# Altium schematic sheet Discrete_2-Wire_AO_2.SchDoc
size 431 x 279 mm; Date: Not shown in title block; ApprovedBy: Not shown in title block; CheckedBy: Not shown in title block; Author: Not shown in title block; CompanyName: Not shown in title block; Engineer: Not shown in title block; Organization: Not shown in title block; Address1: Not shown in title block; Address2: Not shown in title block; Address3: Not shown in title block; Address4: Not shown in title block; DocumentNumber: 1; Revision: Use project parameter SCH_Rev; SheetNumber: 1; SheetTotal: 1; PageSetup: Record=PageOptions|CenterHorizontal=True|CenterVertical=True|PrintScale=1.00|XCorrection=1.00|YCorrection=1.00|PrintKind=0|BorderSize=5000000|LeftOffset=0|BottomOffset=0|Orientation=2|PaperLength=1000|PaperWidth=1000|Scale=100|PaperSource=15|PrintQuality=600|MediaType=1|DitherType=10|PaperKind=Letter|PrintScaleMode=1
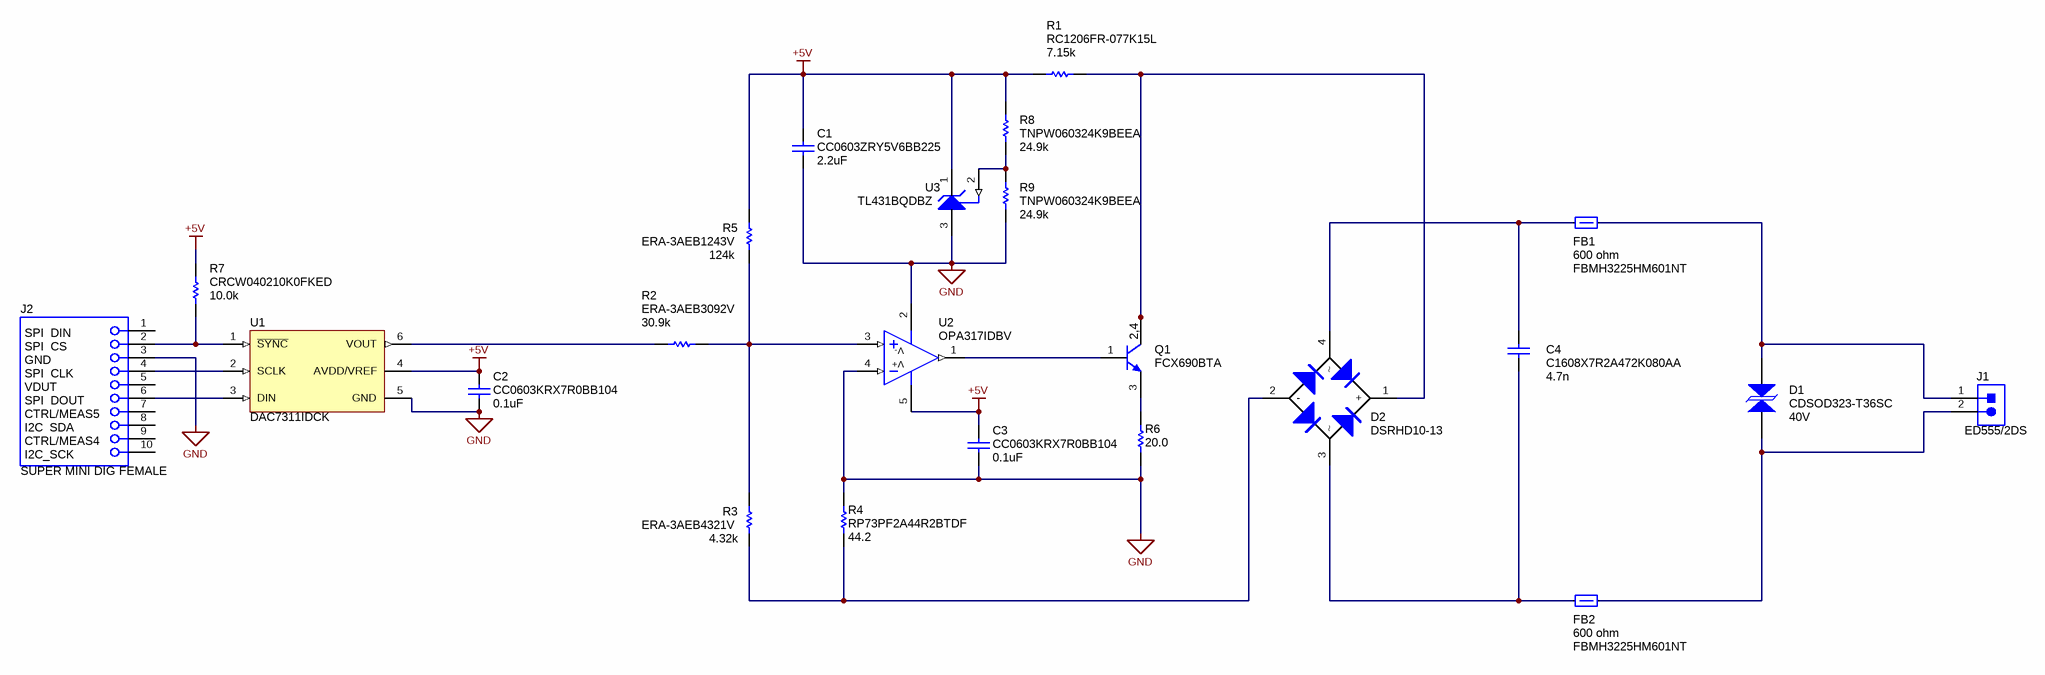
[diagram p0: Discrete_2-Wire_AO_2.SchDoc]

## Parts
C1  CC0603ZRY5V6BB225  value 2.2uF  [0603]
C2  CC0603KRX7R0BB104  value 0.1uF  [0603]
C3  CC0603KRX7R0BB104  value 0.1uF  [0603]
C4  C1608X7R2A472K080AA  value 4.7n  [0603]
D1  CDSOD323-T36SC  value 40V  [sod-323]
D2  DSRHD10-13  [T-MiniDIP]
FB1  FBMH3225HM601NT  value 600 ohm  [1210_H25]
FB2  FBMH3225HM601NT  value 600 ohm  [1210_H25]
J1  ED555/2DS  [TERM_BLK_ED555-2DS]
J2  SUPER MINI DIG FEMALE  [CONN_851-43-010-20-001000]
Q1  FCX690BTA  [SOT-89-3]
R1  RC1206FR-077K15L  value 7.15k  [1206]
R2  ERA-3AEB3092V  value 30.9k  [0603]
R3  ERA-3AEB4321V  value 4.32k  [0603]
R4  RP73PF2A44R2BTDF  value 44.2  [0805]
R5  ERA-3AEB1243V  value 124k  [0603]
R6  value 20.0  [0603]  (hidden comment: CRCW060320R0FKEA)
R7  CRCW040210K0FKED  value 10.0k  [0402]
R8  TNPW060324K9BEEA  value 24.9k  [0603]
R9  TNPW060324K9BEEA  value 24.9k  [0603]
U1  DAC7311IDCK  [DCK0006A_N]
U2  OPA317IDBV  [DBV0005A_N]
U3  TL431BQDBZ  [DBZ0003A_N]

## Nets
+5V: C1.1 C2.1 C3.1 R1.2 R5.2 R7.2 R8.2 U1.4(AVDD/VREF) U2.5(V+) U3.1(CATHODE)
GND: C1.2 C2.2 C3.2 J2.3 R4.2 R6.1 R9.1 U1.5(GND) U2.2(V-) U2.4(IN-) U3.3(ANODE)
NetC4_1: C4.1 D2.4 FB1.1
NetC4_2: C4.2 D2.3 FB2.1
NetD1_1: D1.1 FB1.2 J1.1
NetD1_2: D1.2 FB2.2 J1.2
NetD2_1: D2.1(+) Q1.2(C) Q1.4(C) R1.1
NetD2_2: D2.2(-) R3.1 R4.1
NetJ2_2: J2.2 R7.1 U1.1(~{SYNC})
NetJ2_4: J2.4 U1.2(SCLK)
NetJ2_6: J2.6 U1.3(DIN)
NetQ1_1: Q1.1(B) U2.1(OUT)
NetQ1_3: Q1.3(E) R6.2
NetR2_1: R2.1 U1.6(VOUT)
NetR2_2: R2.2 R3.2 R5.1 U2.3(IN+)
NetR8_1: R8.1 R9.2 U3.2(REF)

Not connected (* = marked no-connect by the designer): J2 1 5 7 8 9 10

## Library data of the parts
C1 = Capacitor: CAP CER 2.2UF 10V Y5V 0603; Manufacturer: Yageo; Polarized: N; U/M: EA; Tolerance_%: -20%, +80%; TempCo: Y5V (F)
C2 C3 = Capacitor: CAP CER 0.1UF 100V 10% X7R 0603; Manufacturer: Yageo; Polarized: N; U/M: EA
C4 = Capacitor: CAP CER 4700PF 100V 10% X7R 0603; Manufacturer: TDK; Polarized: N; U/M: EA
D1 = SMAJ15CA: TVS DIODE 36VWM 60VC SOD323; Manufacturer: Bourns Inc
D2 = DSRHD10-13: Diode, Switching-Bridge, 1000V, 1A, 5.0x1.21x6.2mm; Manufacturer: Diodes Inc.; U/M: EA; Vf_V: 1.15; Value2: 1.15V; Io_A: 1; Vr_V: 1000; TJmax_C: 150
FB1 FB2 = FBMH3225HM601NT: 3A Ferrite Bead, 600 ohm @ 100MHz, SMD; Manufacturer: Taiyo Yuden; Imax_A: 3; DCR_ohm: 0.042; Value1: 0.042 ohm; ZTyp@100MHz_Ohm: 600; U/M: EA
J1 = ED555/2DS: Terminal Block, 6A, 3.5mm Pitch, 2-Pos, TH; Manufacturer: On-Shore Technology; SymbolCreator: a0412235; CompType: Connector; U/M: EA
J2 = 851-43-010-20-001000: Receptacle, 50mil 10x1, R/A, TH; Manufacturer: Mill-Max; SymbolCreator: a0411947; U/M: EA
Q1 = FCX690BTA, Diodes Inc.: Transistor, NPN, 45V, 1A, SOT-89; CompType: BJT; PNP: 0; NPN: 1; Vceo_V: 45; Vcesat1_V: 0.08; Value: 0.08V; TaMin_C: -55; TaMax_C: 150; U/M: EA
R1 = Resistor: RES 7.15K OHM 1/4W 1% 1206 SMD; Manufacturer: Yageo; U/M: EA; Power_W: 0.25W, 1/4W; TempCo: ±100ppm/°C
R2 = Resistor: RES 30.9K OHM 1/10W .1% 0603 SMD; Manufacturer: Panasonic; U/M: EA; Tolerance_%: ±0.1%; Power_W: 0.1W, 1/10W; TempCo: ±25ppm/°C
R3 = Resistor: RES 4.32K OHM 1/10W .1% 0603 SMD; Manufacturer: Panasonic; U/M: EA; Tolerance_%: ±0.1%; Power_W: 0.1W, 1/10W; TempCo: ±25ppm/°C
R4 = Resistor: RES 44.2 OHM 1/4W 0.1% 0805; Manufacturer: TE Connectivity; U/M: EA; Power_W: 0.25W, 1/4W; TempCo: ±25ppm/°C
R5 = Resistor: RES 124K OHM 1/10W .1% 0603 SMD; Manufacturer: Panasonic; U/M: EA; Tolerance_%: ±0.1%; Power_W: 0.1W, 1/10W; TempCo: ±25ppm/°C
R6 = CRCW060320R0FKEA: RES, 20.0 ohm, 1%, 0.1W, 0603; Manufacturer: Vishay-Dale; CompType: Resistor; Res_ohm: 20; Value_Code: 20R0; Tolerance_%: 1; Power_W: 0.1; VDC_V: 75; TempCo: 100 ppm/C; EIA_Code: E96; U/M: EA
R7 = CRCW040210K0FKED: RES, 10.0k ohm, 1%, 0.063W, 0402; Manufacturer: Vishay-Dale; CompType: Resistor; Res_ohm: 10000; Value_Code: 10k0; Tolerance_%: 1; Power_W: 0.063; VDC_V: 50; TempCo: 100 ppm/C; EIA_Code: E96; U/M: EA
R8 R9 = Resistor: RES 24.9K OHM 1/10W 0.1% 0603; Manufacturer: Vishay Dale; U/M: EA; Power_W: 0.1W, 1/10W; TempCo: ±25ppm/°C
U1 = DAC7311IDCK: 2.0V to 5.5V, 80µA, 12-Bit, Low-Power, Single-Channel, Digital-to-Analog Converters in SC70 Package, DCK0006A; Alternate Manufacturer: None; Manufacturer: Texas Instruments; SymbolCreator: a0411947; CompType: IC; U/M: EA
U2 = OPA317IDBV: Low-Offset, Rail-to-Rail I/O Operational Amplifier, DBV0005A; Alternate Manufacturer: None; Manufacturer: Texas Instruments; CompType: IC; U/M: EA
U3 = TL431BQDBZ: PRECISION PROGRAMMABLE REFERENCE, DBZ0003A; Alternate Manufacturer: None; Manufacturer: Texas Instruments; SymbolCreator: a0412235; CompType: IC; U/M: EA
